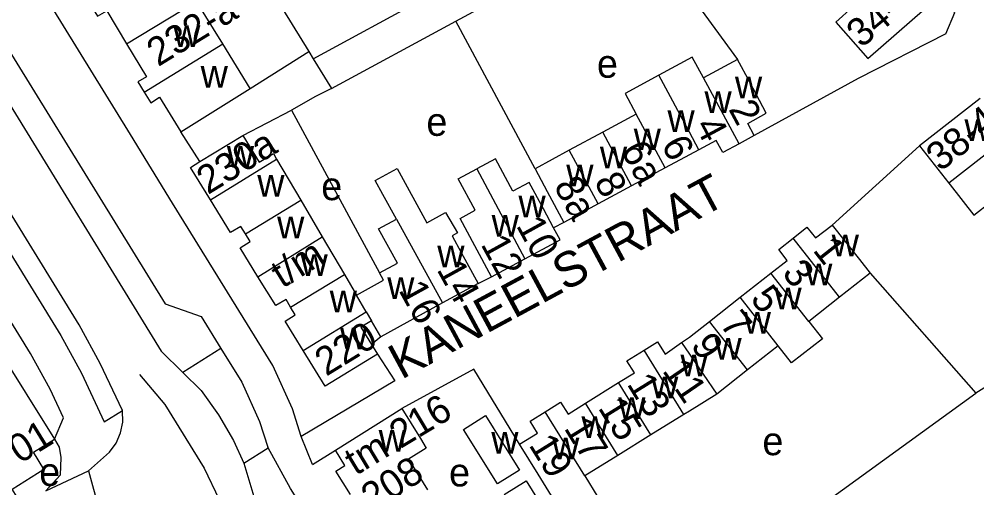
# Model space of a CAD drawing. Extents: x 159902 to 161769, y 383692 to 384875.
# Drawn here: x 160604.7 to 160740.8, y 384330.9 to 384397.4 of the extents above; entities that cross this region are included whole.
import ezdxf

# ---------------------------------------------------------------- set-up
doc = ezdxf.new("R2010")
doc.units = 0
for name, color, linetype in [('BLT_Basislijn', 7, 'Continuous'), ('BLT_Bebouwing', 7, 'Continuous'), ('BLT_Centroide', 7, 'Continuous'), ('BLT_Huisnummer', 7, 'Continuous'), ('BLT_Huisnummer_ tussenligend', 7, 'Continuous'), ('BLT_Huisnummer_reeks', 7, 'Continuous'), ('BLT_Onderverdeling_panden', 7, 'Continuous'), ('BLT_Straatnaam', 7, 'Continuous'), ('BLT_Vlakafsluiter', 7, 'Continuous')]:
    doc.layers.add(name, color=color, linetype=linetype)

msp = doc.modelspace()

# ---------------------------------------------------------------- linework, layer by layer
at = {"layer": 'BLT_Basislijn'}
for p, q in [((160623.2, 384429.9), (160645.9, 384392.82)), ((160666.8, 384397.15), (160692.62, 384411.14)), ((160588.59, 384409.38), (160624.95, 384350.29)), ((160646.52, 384391.81), (160680.34, 384410.17)), ((160700, 384401.04), (160706.82, 384391.71)), ((160649.12, 384387.57), (160666.8, 384397.15)), ((160678.07, 384376.2), (160666.8, 384397.15)), ((160637.59, 384387.57), (160645.9, 384392.82)), ((160645.9, 384392.82), (160646.52, 384391.81)), ((160646.52, 384391.81), (160649.12, 384387.57)), ((160649.12, 384387.57), (160646.85, 384386.44)), ((160646.85, 384386.44), (160643.46, 384384.53)), ((160636.52, 384380.94), (160643.46, 384384.53)), ((160643.46, 384384.53), (160655.94, 384361.41)), ((160630.43, 384377.21), (160627.74, 384381.46)), ((160732.71, 384379.43), (160720.29, 384368.21)), ((160682.14, 384368.58), (160680.7, 384367.83)), ((160725.7, 384361.39), (160740.71, 384344.36)), ((160669.98, 384359.93), (160671.86, 384360.87)), ((160630.61, 384355.23), (160633.4, 384350.71)), ((160656.15, 384352.35), (160654.82, 384351.26)), ((160633.4, 384350.71), (160628.01, 384347.29)), ((160624.95, 384350.29), (160628.01, 384347.29)), ((160646.45, 384334.23), (160644.83, 384338.21)), ((160609.76, 384337.83), (160610.43, 384336.68)), ((160636.68, 384334.42), (160640.14, 384336.58)), ((160640.14, 384336.58), (160640.07, 384336.7)), ((160646.45, 384334.23), (160649.69, 384336.24)), ((160636.68, 384334.42), (160638.08, 384329.66)), ((160608.54, 384330.46), (160614.59, 384333.31))]:
    msp.add_line(p, q, dxfattribs=at)
for points in [[(160609.76, 384337.83), (160611.06, 384340.84), (160609.15, 384344.91), (160606.34, 384350), (160546.95, 384446.54), (160528.88, 384473.45)], [(160546.58, 384460.85), (160544.3, 384459.45), (160551.15, 384449.24), (160610.66, 384352.52), (160613.6, 384347.18), (160616.84, 384340.29), (160619.41, 384341.88)], [(160619.41, 384341.88), (160616.28, 384348.55), (160613.26, 384354.03), (160553.68, 384450.86), (160550.6, 384455.44), (160547.04, 384460.09), (160546.58, 384460.85)], [(160644.83, 384338.21), (160643.59, 384342.14), (160640.8, 384348.26), (160626.55, 384371.32), (160620.56, 384381.08), (160605.79, 384405.03), (160602.56, 384409.58), (160597.68, 384415)], [(160599.65, 384405.04), (160595.1, 384406.28), (160625.48, 384357.01), (160630.61, 384355.23)], [(160736.44, 384395.35), (160737.72, 384398.4), (160733.22, 384403.87)], [(160736.44, 384395.35), (160723.98, 384389.03), (160709.2, 384380.9)], [(160633.4, 384350.71), (160636.38, 384345.9), (160638.92, 384340.34), (160640.07, 384336.7)], [(160655.66, 384349.9), (160658.11, 384346.1), (160644.83, 384338.21)], [(160675.85, 384337.1), (160669.38, 384347.74), (160659.12, 384342.15)], [(160755.67, 384335.37), (160746.29, 384347.86), (160740.71, 384344.36)], [(160621.83, 384346.99), (160625.43, 384342.73), (160631.02, 384333.68), (160633.19, 384329.27)], [(160628.01, 384347.29), (160630.61, 384344.74), (160633.09, 384341.29), (160635.23, 384337.62), (160636.68, 384334.42)], [(160718.71, 384329.18), (160719.85, 384329.26), (160740.71, 384344.36)], [(160614.59, 384333.31), (160617.57, 384335.97), (160618.54, 384337.27), (160619.17, 384338.71), (160619.47, 384340.21), (160619.41, 384341.88)], [(160610.43, 384336.68), (160610.68, 384335.23), (160610.56, 384332.7), (160608.54, 384330.46)], [(160690.65, 384258.45), (160686.25, 384263.77), (160682.97, 384267.55), (160643.33, 384330.83), (160640.14, 384336.58)]]:
    msp.add_lwpolyline(points, dxfattribs=at)
at = {"layer": 'BLT_Bebouwing'}
for p, q in [((160633.67, 384393.94), (160629.97, 384399.96)), ((160637.59, 384387.57), (160633.67, 384393.94)), ((160706.82, 384391.71), (160702.02, 384389.12)), ((160627.74, 384381.46), (160637.59, 384387.57)), ((160741.29, 384386.15), (160732.71, 384379.43)), ((160692.44, 384383.95), (160687.68, 384381.38)), ((160630.43, 384377.21), (160636.52, 384380.94)), ((160636.52, 384380.94), (160638.87, 384377.12)), ((160709.2, 384380.9), (160707.06, 384379.75)), ((160732.71, 384379.43), (160736.86, 384374.14)), ((160682.92, 384378.82), (160678.07, 384376.2)), ((160700, 384378.18), (160696.53, 384376.32)), ((160701.33, 384378.9), (160700, 384378.18)), ((160629.11, 384376.39), (160630.43, 384377.21)), ((160631.95, 384371.77), (160629.11, 384376.39)), ((160696.53, 384376.32), (160691.77, 384373.76)), ((160691.77, 384373.76), (160687.01, 384371.2)), ((160644.76, 384371.74), (160647.83, 384366.52)), ((160687.01, 384371.2), (160682.14, 384368.58)), ((160647.83, 384366.52), (160650.96, 384361.19)), ((160671.86, 384360.87), (160676.62, 384363.43)), ((160707.2, 384357.95), (160711.57, 384361.38)), ((160725.7, 384361.39), (160721.34, 384357.96)), ((160650.96, 384361.19), (160652.67, 384358.26)), ((160669.98, 384359.93), (160664.9, 384357.15)), ((160702.83, 384354.52), (160707.2, 384357.95)), ((160721.34, 384357.96), (160716.97, 384354.52)), ((160664.9, 384357.15), (160656.15, 384352.35)), ((160656.15, 384352.35), (160654.81, 384354.63)), ((160700, 384352.3), (160702.83, 384354.52)), ((160600.81, 384352.09), (160609.76, 384337.83)), ((160698.89, 384351.52), (160700, 384352.3)), ((160654.82, 384351.26), (160655.66, 384349.9)), ((160712.61, 384351.08), (160708.24, 384347.65)), ((160708.24, 384347.65), (160703.88, 384344.21)), ((160685.24, 384342.92), (160689.92, 384345.84)), ((160703.88, 384344.21), (160700, 384341.81)), ((160649.69, 384336.24), (160659.12, 384342.15)), ((160667.9, 384339.21), (160671.03, 384341.16)), ((160671.03, 384341.16), (160675.86, 384333.44)), ((160699.19, 384341.31), (160694.5, 384338.41)), ((160700, 384341.81), (160699.19, 384341.31)), ((160672.73, 384331.48), (160667.9, 384339.21)), ((160694.5, 384338.41), (160689.82, 384335.52)), ((160689.82, 384335.52), (160685.13, 384332.62)), ((160660.06, 384334.97), (160662.76, 384330.63)), ((160675.86, 384333.44), (160672.73, 384331.48)), ((160673.68, 384329.94), (160676.81, 384331.9)), ((160676.81, 384331.9), (160681.62, 384324.16))]:
    msp.add_line(p, q, dxfattribs=at)
for points in [[(160614.97, 384399.34), (160615.89, 384397.85), (160617.19, 384398.61), (160620.02, 384393.93)], [(160723.23, 384399.17), (160720.82, 384397.03), (160725.36, 384391.84), (160733.49, 384398.96)], [(160620.02, 384393.93), (160622.85, 384389.26), (160621.6, 384388.56), (160622.52, 384387.06)], [(160702.02, 384389.12), (160700.37, 384392.02), (160695.65, 384389.47)], [(160709.2, 384380.9), (160708.29, 384382.63), (160710.92, 384384.07), (160708.56, 384388.47), (160706.82, 384391.71)], [(160695.65, 384389.47), (160690.85, 384386.89), (160692.44, 384383.95)], [(160622.52, 384387.06), (160623.45, 384385.57), (160624.7, 384386.35), (160627.74, 384381.46)], [(160687.68, 384381.38), (160682.92, 384378.82)], [(160707.06, 384379.75), (160704.75, 384378.51), (160703.8, 384380.22), (160701.33, 384378.9)], [(160638.87, 384377.12), (160640.87, 384378.35), (160641.34, 384377.55)], [(160680.7, 384367.83), (160679.26, 384370.52), (160677.24, 384374.27), (160674.89, 384373.01), (160672.43, 384377.59), (160669.79, 384376.17)], [(160641.34, 384377.55), (160644.76, 384371.74)], [(160658.36, 384369.04), (160656.45, 384372.53), (160655.35, 384374.55), (160658.45, 384376.25), (160662.69, 384368.53), (160665.35, 384369.99), (160667.02, 384367.09), (160666.27, 384366.68), (160667.57, 384364.32), (160669.98, 384359.93)], [(160671.86, 384360.87), (160669.49, 384365.28), (160667.41, 384369.16), (160669.54, 384370.3), (160667.15, 384374.75), (160669.79, 384376.17)], [(160678.07, 384376.2), (160679.78, 384372.99), (160682.14, 384368.58)], [(160736.86, 384374.14), (160737.05, 384373.9), (160740.4, 384369.62), (160742.83, 384371.52)], [(160636.9, 384366.94), (160636.24, 384368.02), (160634.79, 384367.16), (160631.95, 384371.77)], [(160655.94, 384361.41), (160658.49, 384362.81), (160655.83, 384367.65), (160658.36, 384369.04)], [(160714.73, 384366.34), (160716.7, 384367.89), (160717.92, 384366.38), (160720.29, 384368.21)], [(160720.29, 384368.21), (160724.17, 384363.31), (160725.7, 384361.39)], [(160638.68, 384360.88), (160636.15, 384364.99), (160637.56, 384365.86), (160636.9, 384366.94)], [(160676.62, 384363.43), (160681.62, 384366.11), (160680.7, 384367.83)], [(160711.57, 384361.38), (160713.89, 384363.19), (160712.71, 384364.74), (160714.73, 384366.34)], [(160652.67, 384358.26), (160656.51, 384360.37), (160655.94, 384361.41)], [(160643.33, 384356.54), (160642.67, 384357.62), (160641.22, 384356.77), (160638.68, 384360.88)], [(160645.12, 384350.41), (160642.56, 384354.57), (160643.99, 384355.45), (160643.33, 384356.54)], [(160654.81, 384354.63), (160653.31, 384353.71), (160654.82, 384351.26)], [(160716.97, 384354.52), (160718.89, 384352.08), (160714.52, 384348.65), (160712.61, 384351.08)], [(160655.66, 384349.9), (160648.25, 384345.34), (160645.12, 384350.41)], [(160689.92, 384345.84), (160692.18, 384347.25), (160691.12, 384348.94), (160693.55, 384350.44)], [(160693.55, 384350.44), (160695.45, 384351.62), (160696.57, 384349.89), (160698.89, 384351.52)], [(160679.51, 384341.71), (160681.68, 384343.05), (160682.76, 384341.38), (160685.24, 384342.92)], [(160659.12, 384342.15), (160661.76, 384337.9), (160662.6, 384336.55), (160660.06, 384334.97)], [(160675.85, 384337.1), (160678.42, 384338.69), (160677.36, 384340.39), (160679.51, 384341.71)], [(160605.16, 384328.43), (160603.75, 384330.72), (160608.27, 384333.57), (160606.77, 384335.97), (160609.76, 384337.83)], [(160682.31, 384326.7), (160678.49, 384332.85), (160675.85, 384337.1)], [(160651.85, 384329.95), (160649.76, 384333.29), (160651.04, 384334.09), (160649.69, 384336.24)], [(160685.13, 384332.62), (160686.99, 384329.6), (160682.31, 384326.7)]]:
    msp.add_lwpolyline(points, dxfattribs=at)
at = {"layer": 'BLT_Onderverdeling_panden'}
for p, q in [((160620.02, 384393.93), (160629.97, 384399.96)), ((160622.52, 384387.06), (160633.67, 384393.94)), ((160700, 384381.38), (160695.65, 384389.47)), ((160707.06, 384379.75), (160702.02, 384389.12)), ((160696.53, 384376.32), (160692.44, 384383.95)), ((160747.82, 384382.72), (160736.86, 384374.14)), ((160691.77, 384373.76), (160687.68, 384381.38)), ((160701.33, 384378.9), (160700, 384381.38)), ((160687.01, 384371.2), (160682.92, 384378.82)), ((160631.95, 384371.77), (160641.34, 384377.55)), ((160669.79, 384376.17), (160676.62, 384363.43)), ((160636.9, 384366.94), (160644.76, 384371.74)), ((160658.36, 384369.04), (160664.9, 384357.15)), ((160638.68, 384360.88), (160647.83, 384366.52)), ((160721.34, 384357.96), (160714.73, 384366.34)), ((160716.97, 384354.52), (160711.57, 384361.38)), ((160643.33, 384356.54), (160650.96, 384361.19)), ((160654.08, 384355.87), (160652.67, 384358.26)), ((160712.61, 384351.08), (160707.2, 384357.95)), ((160645.12, 384350.41), (160654.08, 384355.87)), ((160708.24, 384347.65), (160702.83, 384354.52)), ((160699.19, 384341.31), (160693.55, 384350.44)), ((160698.89, 384351.52), (160700, 384349.9)), ((160700, 384349.9), (160703.88, 384344.21)), ((160694.5, 384338.41), (160689.92, 384345.84)), ((160689.82, 384335.52), (160685.24, 384342.92)), ((160685.13, 384332.62), (160679.51, 384341.71))]:
    msp.add_line(p, q, dxfattribs=at)
msp.add_lwpolyline([(160654.08, 384355.87), (160654.81, 384354.63)], dxfattribs=at)
at = {"layer": 'BLT_Vlakafsluiter'}
msp.add_line((160614.59, 384333.31), (160616.32, 384327.07), dxfattribs=at)

# ---------------------------------------------------------------- texts
at = {"layer": 'BLT_Centroide'}
for s, p in [('w', (160626.63, 384393.5)), ('e', (160686.86, 384389.12)), ('w', (160630.54, 384387.69)), ('w', (160706.47, 384386.19)), ('w', (160702.14, 384384.11)), ('w', (160696.88, 384381.42)), ('e', (160662.62, 384380.87)), ('w', (160739.08, 384380.16)), ('w', (160692.08, 384378.84)), ('w', (160634.27, 384376.34)), ('w', (160687.28, 384376.25)), ('w', (160682.5, 384373.69)), ('w', (160638.59, 384372.25)), ('e', (160647.68, 384371.74)), ('w', (160675.7, 384369.3)), ('w', (160671.89, 384366.56)), ('w', (160641.41, 384366.31)), ('w', (160720.22, 384363.77)), ('w', (160644.74, 384361)), ('w', (160664.17, 384362.2)), ('w', (160716.45, 384359.67)), ('w', (160657.06, 384357.73)), ('w', (160648.88, 384355.81)), ('w', (160712.08, 384356.23)), ('w', (160707.72, 384352.8)), ('w', (160650.34, 384350.59)), ('w', (160703.56, 384349.12)), ('w', (160698.72, 384346.75)), ('w', (160694.55, 384343.62)), ('w', (160689.88, 384340.69)), ('w', (160684.66, 384337.97)), ('w', (160655.83, 384336.06)), ('w', (160671.84, 384335.78)), ('e', (160710.37, 384335.54)), ('w', (160680.48, 384334.94)), ('e', (160607.6, 384331.18)), ('e', (160665.84, 384331.11))]:
    msp.add_text(s, height=4, dxfattribs=at).set_placement(p)
at = {"layer": 'BLT_Huisnummer'}
for s, rotation, p in [('2', 298.2796, (160705.49, 384384.67)), ('6', 298.2765, (160695.92, 384379.61)), ('6a', 298.2792, (160690.16, 384378.84)), ('8a', 298.7965, (160680.65, 384373.77)), ('8', 298.2116, (160686.38, 384374.39)), ('10', 298.7897, (160675.3, 384368.15)), ('1', 308.2245, (160717.42, 384364.62)), ('16', 298.7861, (160658.6, 384358.99)), ('5', 308.2246, (160708.53, 384357.7)), ('9', 304.2964, (160700.09, 384351.15)), ('13', 301.7236, (160691.03, 384345.66)), ('19', 301.8778, (160677.09, 384337))]:
    msp.add_text(s, height=4, rotation=rotation, dxfattribs=at).set_placement(p)
at = {"layer": 'BLT_Huisnummer_ tussenligend'}
for s, rotation, p in [('4', 298.2796, (160700.69, 384382.29)), ('12', 298.7897, (160670.27, 384365.49)), ('14', 298.7897, (160664.02, 384361.91)), ('3', 308.2245, (160713.04, 384361.35)), ('7', 308.2246, (160704.18, 384354.09)), ('11', 304.2964, (160696.05, 384347.54)), ('15', 301.7236, (160686.93, 384342.28)), ('17', 301.7236, (160682.09, 384339.39))]:
    msp.add_text(s, height=4, rotation=rotation, dxfattribs=at).set_placement(p)
at = {"layer": 'BLT_Huisnummer_reeks'}
for s, rotation, p in [('232-a t/m f', 31.6007, (160624.49, 384390.61)), ('34-36', 40.1731, (160724.45, 384393.24)), ('38-40', 38.0734, (160735.65, 384375.7)), ('230a', 31.4311, (160631.57, 384372.46)), ('t/m', 31.5976, (160642.15, 384359.15)), ('220', 31.5976, (160648.38, 384346.67)), ('tm 216', 31.0819, (160652.57, 384332.57)), ('187 01', 31.6119, (160595.97, 384328.79)), ('208', 32.2823, (160654.99, 384327.46))]:
    msp.add_text(s, height=4, rotation=rotation, dxfattribs=at).set_placement(p)
at = {"layer": 'BLT_Straatnaam'}
msp.add_text('KANEELSTRAAT', height=4.9999, rotation=28.3488, dxfattribs=at).set_placement((160659.06, 384346.22))

doc.saveas('drawing.dxf')
